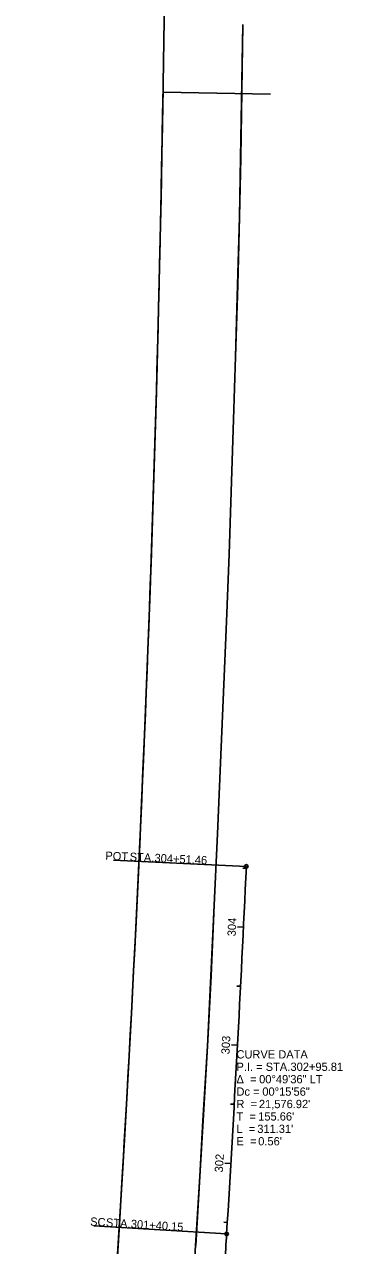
# Model space of a CAD drawing. Extents: x 172104 to 172774, y 250510 to 260293.
# Drawn here: x 172392 to 172661, y 257029 to 258062 of the extents above; entities that cross this region are included whole.
import ezdxf

# ---------------------------------------------------------------- set-up
doc = ezdxf.new("R2010")
doc.units = 0
for name, color, linetype in [('DT_P_Contour_Minor', 7, 'Continuous'), ('DT_P_Spot_Elevations', 7, 'Continuous'), ('DT_P_Terrain_Boundary', 7, 'Continuous'), ('DT_P_Triangles', 7, 'Continuous'), ('DT_P_Void', 7, 'Continuous'), ('DT_X_Contour_Minor', 7, 'Continuous'), ('DT_X_Spot_Elev', 7, 'Continuous')]:
    doc.layers.add(name, color=color, linetype=linetype)

msp = doc.modelspace()

# ---------------------------------------------------------------- linework, layer by layer
at = {"layer": 'DT_P_Contour_Minor'}
msp.add_arc((151025.9, 258352.5), 21576.9, 356.51076, 357.33743, dxfattribs=at)
msp.add_arc((151025.9, 258352.5), 21576.9, 356.51076, 357.33743, dxfattribs=at)
msp.add_arc((151025.9, 258352.5), 21576.9, 356.51076, 357.33743, dxfattribs=at)
msp.add_open_spline([(172551.8, 256839.6), (172552.5, 256856.3), (172554.1, 256889.6), (172556.8, 256939.5), (172559.7, 256989.4), (172561.8, 257022.7), (172562.8, 257039.3)], degree=3, dxfattribs=at)
msp.add_open_spline([(172551.8, 256839.6), (172552.5, 256856.3), (172554.1, 256889.6), (172556.8, 256939.5), (172559.7, 256989.4), (172561.8, 257022.7), (172562.8, 257039.3)], degree=3, dxfattribs=at)
at = {"layer": 'DT_P_Spot_Elevations'}
for p, q in [((172579.5, 257350.2), (172467.1, 257355.4)), ((172562.8, 257039.3), (172450.5, 257046.1))]:
    msp.add_line(p, q, dxfattribs=at)
for centre in [(172579.5, 257350.2), (172562.8, 257039.3)]:
    msp.add_circle(centre, 1.5, dxfattribs=at)
at = {"layer": 'DT_P_Terrain_Boundary'}
msp.add_arc((151025.9, 258352.5), 21485.9, 353.94188, 0.0466, dxfattribs=at)
msp.add_arc((151025.9, 258352.5), 21485.9, 353.94188, 0.0466, dxfattribs=at)
at = {"layer": 'DT_P_Triangles'}
for p, q in [((172574.6, 257949.4), (172576.4, 258062.3)), ((172574.7, 257949.4), (172576.5, 258062.3)), ((172573.6, 257899.5), (172574.6, 257949.4)), ((172573.7, 257899.5), (172574.7, 257949.4)), ((172572.1, 257841.7), (172573.6, 257899.5)), ((172572.2, 257841.7), (172573.7, 257899.5)), ((172570.3, 257781.2), (172572.1, 257841.7)), ((172570.4, 257781.2), (172572.2, 257841.7)), ((172568.6, 257728), (172570.3, 257781.2)), ((172568.7, 257728), (172570.4, 257781.2)), ((172566.6, 257666.9), (172568.6, 257728)), ((172566.7, 257666.9), (172568.7, 257728)), ((172564.9, 257614.3), (172566.6, 257666.9)), ((172565, 257614.3), (172566.7, 257666.9)), ((172562.7, 257557.2), (172564.9, 257614.3)), ((172562.7, 257557.2), (172565, 257614.3)), ((172560.4, 257504), (172562.7, 257557.2)), ((172560.5, 257504), (172562.7, 257557.2)), ((172557.5, 257437.7), (172560.4, 257504)), ((172557.6, 257437.7), (172560.5, 257504)), ((172555, 257377.8), (172557.5, 257437.7)), ((172555, 257377.8), (172557.6, 257437.7)), ((172552.3, 257317.5), (172555, 257377.8)), ((172552.3, 257317.5), (172555, 257377.8)), ((172549.5, 257257.7), (172552.3, 257317.5)), ((172549.6, 257257.7), (172552.3, 257317.5)), ((172546.5, 257198.2), (172549.5, 257257.7)), ((172546.5, 257198.2), (172549.6, 257257.7)), ((172542.8, 257135.2), (172546.5, 257198.2)), ((172542.9, 257135.2), (172546.5, 257198.2)), ((172540, 257087.8), (172542.8, 257135.2)), ((172540.1, 257087.8), (172542.9, 257135.2)), ((172536.6, 257029.5), (172540, 257087.8)), ((172536.7, 257029.5), (172540.1, 257087.8)), ((172532.5, 256965.3), (172536.6, 257029.5))]:
    msp.add_line(p, q, dxfattribs=at)
at = {"layer": 'DT_P_Void'}
for p, q in [((172579.4, 257348.7), (172576.4, 257348.8)), ((172577, 257298.8), (172572, 257299)), ((172574.5, 257248.8), (172571.5, 257249)), ((172571.9, 257198.9), (172566.9, 257199.2)), ((172569.2, 257149), (172566.2, 257149.1)), ((172566.3, 257099), (172561.4, 257099.3)), ((172563.4, 257049.1), (172560.4, 257049.3))]:
    msp.add_line(p, q, dxfattribs=at)
at = {"layer": 'DT_X_Contour_Minor'}
msp.add_line((172509, 258004.9), (172600, 258003.4), dxfattribs=at)
msp.add_arc((151025.9, 258352.5), 21485.9, 355.97974, 359.07307, dxfattribs=at)

# ---------------------------------------------------------------- texts
at = {"layer": 'DT_P_Spot_Elevations'}
for s, rotation, p in [('POT', 357.3374, (172460.1, 257355.8)), (' STA. ', 357.3374, (172478.1, 257355)), ('304+51.46', 357.3374, (172501.7, 257353.9)), ('SC', 356.5108, (172447.2, 257046.4)), (' STA. ', 356.5108, (172458, 257045.8)), ('301+40.15', 356.5108, (172481.6, 257044.4))]:
    msp.add_text(s, height=7, rotation=rotation, dxfattribs=at).set_placement(p)
at = {"layer": 'DT_P_Void'}
for s, rotation, p in [('304', 87.2008, (172570.4, 257290.9)), ('303', 86.9352, (172565.2, 257191.1)), ('302', 86.6697, (172559.6, 257091.2))]:
    msp.add_text(s, height=7, rotation=rotation, dxfattribs=at).set_placement(p)
at = {"layer": 'DT_X_Spot_Elev'}
for s, p in [('CURVE DATA', (172571.1, 257187.7)), ('P.I. = STA. ', (172571.1, 257177.2)), ('302+95.81', (172616.8, 257177.2)), ('Δ  = ', (172571.1, 257166.7)), ('00°49\'36" LT', (172590.3, 257166.7)), ('Dc = ', (172571.1, 257156.2)), ('00°15\'56"', (172593, 257156.2)), ('R  = ', (172571.1, 257145.7)), ("21,576.92'", (172590.1, 257145.7)), ('T  = ', (172571.1, 257135.2)), ("155.66'", (172589.5, 257135.2)), ('L  = ', (172571.1, 257124.7)), ("311.31'", (172588.7, 257124.7)), ('E  = ', (172571.1, 257114.2)), ("0.56'", (172589.5, 257114.2))]:
    msp.add_text(s, height=7, dxfattribs=at).set_placement(p)

doc.saveas('drawing.dxf')
